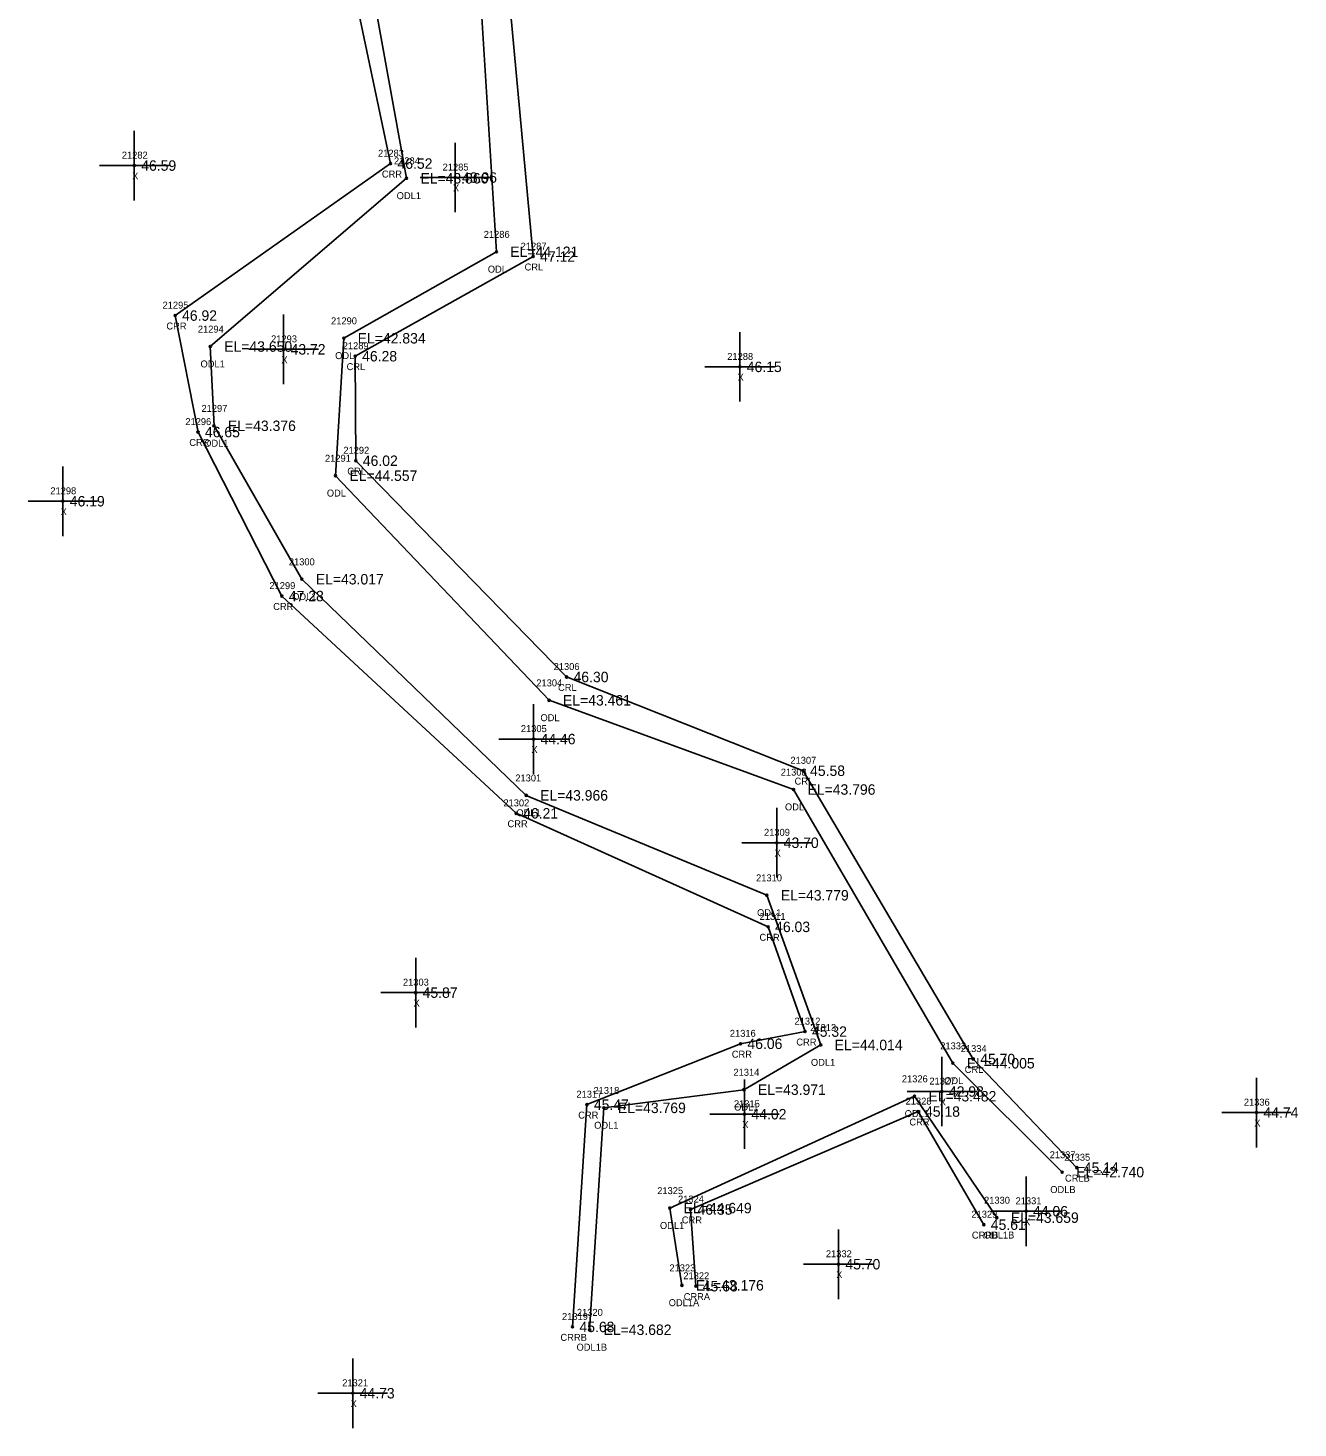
# Model space of a CAD drawing. Extents: x 2420351 to 2422725, y 845330 to 846558.
# Drawn here: x 2421764.6 to 2421947.1, y 845330.1 to 845531.3 of the extents above; entities that cross this region are included whole.
import ezdxf

# ---------------------------------------------------------------- set-up
doc = ezdxf.new("R2010")
doc.units = 0
for name, color, linetype in [('RD_EX_H2O', 7, 'Continuous'), ('RD_EX_H2O_txCode', 7, 'Continuous'), ('RD_EX_Misc', 7, 'Continuous'), ('RD_EX_Misc_txCode', 7, 'Continuous'), ('RD_EX_TX_H2O_ELEV', 7, 'Continuous'), ('RD_EX_TX_Misc_ELEV', 7, 'Continuous'), ('RD_SMD_Locator', 7, 'Continuous')]:
    doc.layers.add(name, color=color, linetype=linetype)

msp = doc.modelspace()

# ---------------------------------------------------------------- linework, layer by layer
at = {"layer": 'RD_EX_H2O'}
for points in [[(2421789.64, 845837.83), (2421802.06, 845811.15), (2421810.66, 845784.93), (2421844.56, 845740.42), (2421856.1, 845683.72), (2421854.89, 845664.88), (2421843.25, 845658.16), (2421829.21, 845628.83), (2421830.77, 845610.33), (2421843.38, 845580.1), (2421828.19, 845558.94), (2421831.91, 845499.14), (2421809.98, 845486.71), (2421808.79, 845466.96), (2421839.47, 845434.68), (2421874.6, 845421.86), (2421897.47, 845382.52), (2421913.19, 845366.87)], [(2421810.77, 845819.82), (2421810.76, 845810.56), (2421816.9, 845792.5), (2421822.4, 845786.03), (2421848.72, 845738.63), (2421858.75, 845685.13), (2421860.35, 845662.88), (2421845.9, 845650.47), (2421833.11, 845629.75), (2421840.79, 845614.06), (2421848.44, 845579.41), (2421832.04, 845554.52), (2421837.19, 845498.45), (2421811.62, 845484.13), (2421811.72, 845469.11), (2421841.99, 845438.03), (2421875.97, 845424.56), (2421900.41, 845383.13), (2421915.29, 845367.51)], [(2421769.97, 845784.59), (2421775.7, 845782.12), (2421786.73, 845771.94), (2421823.71, 845730.54), (2421836.28, 845679.34), (2421832.24, 845660.92), (2421820.77, 845638.45), (2421823.1, 845608.96), (2421831.71, 845583.35), (2421823.31, 845575.86), (2421811.92, 845548.94), (2421818.99, 845509.7), (2421790.81, 845485.52), (2421791.34, 845474.13), (2421803.96, 845452.08), (2421836.18, 845421.02), (2421870.76, 845406.66), (2421878.5, 845385.15), (2421867.47, 845378.72), (2421847.36, 845376.11), (2421845.3, 845344.22)], [(2421768.08, 845778.29), (2421776.13, 845776.03), (2421785.06, 845769.58), (2421818.61, 845726.06), (2421831.42, 845677.9), (2421825.05, 845663.86), (2421816.1, 845638.14), (2421820.64, 845608.52), (2421828.09, 845585.14), (2421817.9, 845575.21), (2421808.75, 845549.61), (2421816.7, 845511.81), (2421785.75, 845489.97), (2421789.04, 845473.23), (2421801.09, 845449.66), (2421834.75, 845418.44), (2421870.95, 845402.12), (2421876.24, 845387.07), (2421866.97, 845385.32), (2421844.91, 845376.57), (2421842.84, 845344.63)], [(2421858.56, 845350.61), (2421856.81, 845361.71), (2421891.97, 845377.78), (2421903.8, 845360.33)], [(2421860.55, 845350.48), (2421859.8, 845361.5), (2421892.48, 845375.58), (2421901.93, 845359.32)]]:
    msp.add_lwpolyline(points, dxfattribs=at)
at = {"layer": 'RD_EX_Misc'}
for p, q in [((2421779.89, 845506.53), (2421779.89, 845516.53)), ((2421825.97, 845504.81), (2421825.97, 845514.81)), ((2421774.89, 845511.53), (2421784.89, 845511.53)), ((2421820.97, 845509.81), (2421830.97, 845509.81)), ((2421801.34, 845480.12), (2421801.34, 845490.12)), ((2421866.87, 845477.6), (2421866.87, 845487.6)), ((2421796.34, 845485.12), (2421806.34, 845485.12)), ((2421861.87, 845482.6), (2421871.87, 845482.6)), ((2421769.62, 845458.29), (2421769.62, 845468.29)), ((2421764.62, 845463.29), (2421774.62, 845463.29)), ((2421837.25, 845424.11), (2421837.25, 845434.11)), ((2421832.25, 845429.11), (2421842.25, 845429.11)), ((2421872.18, 845409.21), (2421872.18, 845419.21)), ((2421867.18, 845414.21), (2421877.18, 845414.21)), ((2421820.31, 845387.67), (2421820.31, 845397.67)), ((2421815.31, 845392.67), (2421825.31, 845392.67)), ((2421895.91, 845373.46), (2421895.91, 845383.46)), ((2421867.55, 845370.2), (2421867.55, 845380.2)), ((2421941.1, 845370.43), (2421941.1, 845380.43)), ((2421890.91, 845378.46), (2421900.91, 845378.46)), ((2421862.55, 845375.2), (2421872.55, 845375.2)), ((2421936.1, 845375.43), (2421946.1, 845375.43)), ((2421908, 845356.25), (2421908, 845366.25)), ((2421903, 845361.25), (2421913, 845361.25)), ((2421881.04, 845348.64), (2421881.04, 845358.64)), ((2421876.04, 845353.64), (2421886.04, 845353.64)), ((2421811.27, 845330.1), (2421811.27, 845340.1)), ((2421806.27, 845335.1), (2421816.27, 845335.1))]:
    msp.add_line(p, q, dxfattribs=at)
at = {"layer": 'RD_SMD_Locator'}
for centre in [(2421779.89, 845511.53), (2421816.7, 845511.81), (2421818.99, 845509.7), (2421825.97, 845509.81), (2421831.91, 845499.14), (2421837.19, 845498.45), (2421785.75, 845489.97), (2421790.81, 845485.52), (2421801.34, 845485.12), (2421809.98, 845486.71), (2421811.62, 845484.13), (2421866.87, 845482.6), (2421789.04, 845473.23), (2421791.34, 845474.13), (2421811.72, 845469.11), (2421808.79, 845466.96), (2421769.62, 845463.29), (2421803.96, 845452.08), (2421801.09, 845449.66), (2421841.99, 845438.03), (2421839.47, 845434.68), (2421837.25, 845429.11), (2421875.97, 845424.56), (2421836.18, 845421.02), (2421874.6, 845421.86), (2421834.75, 845418.44), (2421872.18, 845414.21), (2421870.76, 845406.66), (2421870.95, 845402.12), (2421820.31, 845392.67), (2421876.24, 845387.07), (2421866.97, 845385.32), (2421878.5, 845385.15), (2421897.47, 845382.52), (2421900.41, 845383.13), (2421867.47, 845378.72), (2421895.91, 845378.46), (2421844.91, 845376.57), (2421891.97, 845377.78), (2421847.36, 845376.11), (2421867.55, 845375.2), (2421892.48, 845375.58), (2421941.1, 845375.43), (2421913.19, 845366.87), (2421915.29, 845367.51), (2421856.81, 845361.71), (2421859.8, 845361.5), (2421903.8, 845360.33), (2421908, 845361.25), (2421901.93, 845359.32), (2421881.04, 845353.64), (2421858.56, 845350.61), (2421860.55, 845350.48), (2421842.84, 845344.63), (2421845.3, 845344.22), (2421811.27, 845335.1)]:
    msp.add_circle(centre, 0.15, dxfattribs=at)

# ---------------------------------------------------------------- texts
at = {"layer": 'RD_EX_H2O_txCode'}
for s, p in [('21283', (2421814.9, 845512.81)), ('21284', (2421817.19, 845511.7)), ('CRR', (2421815.45, 845509.81)), ('ODL1', (2421817.58, 845506.7)), ('21286', (2421830.09, 845501.14)), ('21287', (2421835.39, 845499.45)), ('CRL', (2421835.96, 845496.45)), ('ODL', (2421830.67, 845496.14)), ('21295', (2421783.95, 845490.97)), ('21290', (2421808.15, 845488.71)), ('CRR', (2421784.5, 845487.97)), ('21294', (2421789.02, 845487.52)), ('21289', (2421809.83, 845485.13)), ('ODL1', (2421789.4, 845482.52)), ('ODL', (2421808.74, 845483.71)), ('CRL', (2421810.39, 845482.13)), ('21297', (2421789.54, 845476.13)), ('21296', (2421787.22, 845474.23)), ('CRR', (2421787.79, 845471.23)), ('ODL1', (2421789.93, 845471.13)), ('21292', (2421809.92, 845470.11)), ('21291', (2421807.28, 845468.96)), ('CRL', (2421810.49, 845467.11)), ('ODL', (2421807.55, 845463.96)), ('21300', (2421802.09, 845454.08)), ('21299', (2421799.3, 845450.66)), ('ODL1', (2421802.56, 845449.08)), ('CRR', (2421799.84, 845447.66)), ('21306', (2421840.13, 845439.03)), ('21304', (2421837.64, 845436.68)), ('CRL', (2421840.76, 845436.03)), ('ODL', (2421838.23, 845431.68)), ('21308', (2421872.76, 845423.86)), ('21307', (2421874.14, 845425.56)), ('21301', (2421834.62, 845423.02)), ('CRL', (2421874.74, 845422.56)), ('21302', (2421832.91, 845419.44)), ('ODL1', (2421834.77, 845418.02)), ('ODL', (2421873.36, 845418.86)), ('CRR', (2421833.5, 845416.44)), ('21310', (2421869.21, 845408.66)), ('ODL1', (2421869.35, 845403.66)), ('21311', (2421869.72, 845403.12)), ('CRR', (2421869.7, 845400.12)), ('21312', (2421874.73, 845388.07)), ('21316', (2421865.44, 845386.32)), ('21313', (2421876.99, 845387.15)), ('CRR', (2421874.99, 845385.07)), ('21333', (2421895.67, 845384.52)), ('21334', (2421898.61, 845384.13)), ('CRR', (2421865.72, 845383.32)), ('ODL1', (2421877.09, 845382.15)), ('21314', (2421865.96, 845380.72)), ('21326', (2421890.15, 845379.78)), ('ODL', (2421896.23, 845379.52)), ('CRL', (2421899.18, 845381.13)), ('21317', (2421843.4, 845377.57)), ('21318', (2421845.85, 845378.11)), ('ODL1', (2421866.06, 845375.72)), ('21328', (2421890.69, 845376.58)), ('CRR', (2421843.66, 845374.57)), ('ODL1', (2421890.56, 845374.78)), ('CRR', (2421891.23, 845373.58)), ('ODL1', (2421845.95, 845373.11)), ('21337', (2421911.39, 845368.87)), ('21335', (2421913.49, 845368.51)), ('CRLB', (2421913.59, 845365.51)), ('21325', (2421855.01, 845363.71)), ('ODLB', (2421911.47, 845363.87)), ('21324', (2421858, 845362.5)), ('21330', (2421901.96, 845362.33)), ('CRR', (2421858.54, 845359.5)), ('21329', (2421900.14, 845360.32)), ('ODL1', (2421855.4, 845358.71)), ('CRRB', (2421900.21, 845357.32)), ('ODL1B', (2421901.92, 845357.33)), ('21323', (2421856.76, 845352.61)), ('21322', (2421858.76, 845351.48)), ('ODL1A', (2421856.66, 845347.61)), ('CRRA', (2421858.81, 845348.48)), ('21319', (2421841.33, 845345.63)), ('21320', (2421843.47, 845346.22)), ('CRRB', (2421841.11, 845342.63)), ('ODL1B', (2421843.42, 845341.22))]:
    msp.add_text(s, height=1, dxfattribs=at).set_placement(p)
at = {"layer": 'RD_EX_Misc_txCode'}
for s, p in [('21282', (2421778.1, 845512.53)), ('21285', (2421824.18, 845510.81)), ('X', (2421779.58, 845509.53)), ('X', (2421825.66, 845507.81)), ('21293', (2421799.54, 845486.12)), ('X', (2421801.02, 845483.12)), ('21288', (2421865.07, 845483.6)), ('X', (2421866.55, 845480.6)), ('21298', (2421767.83, 845464.29)), ('X', (2421769.31, 845461.29)), ('21305', (2421835.42, 845430.11)), ('X', (2421836.93, 845427.11)), ('21309', (2421870.35, 845415.21)), ('X', (2421871.87, 845412.21)), ('21303', (2421818.48, 845393.67)), ('X', (2421820, 845390.67)), ('21327', (2421894.11, 845379.46)), ('21315', (2421866.03, 845376.2)), ('X', (2421895.59, 845376.46)), ('21336', (2421939.28, 845376.43)), ('X', (2421867.23, 845373.2)), ('X', (2421940.78, 845373.43)), ('21331', (2421906.49, 845362.25)), ('X', (2421907.69, 845359.25)), ('21332', (2421879.24, 845354.64)), ('X', (2421880.72, 845351.64)), ('21321', (2421809.76, 845336.1)), ('X', (2421810.96, 845333.1))]:
    msp.add_text(s, height=1, dxfattribs=at).set_placement(p)
at = {"layer": 'RD_EX_TX_H2O_ELEV'}
for s, p in [('46.52', (2421817.7, 845511.06)), ('EL=43.866', (2421820.99, 845508.95)), ('EL=44.121', (2421833.91, 845498.39)), ('47.12', (2421838.19, 845497.7)), ('46.92', (2421786.75, 845489.22)), ('EL=42.834', (2421811.98, 845485.96)), ('EL=43.650', (2421792.81, 845484.77)), ('46.28', (2421812.62, 845483.38)), ('46.65', (2421790.04, 845472.48)), ('EL=43.376', (2421793.34, 845473.38)), ('46.02', (2421812.72, 845468.36)), ('EL=44.557', (2421810.79, 845466.21)), ('EL=43.017', (2421805.96, 845451.33)), ('47.28', (2421802.09, 845448.91)), ('46.30', (2421842.99, 845437.28)), ('EL=43.461', (2421841.47, 845433.93)), ('45.58', (2421876.97, 845423.81)), ('EL=43.966', (2421838.18, 845420.27)), ('EL=43.796', (2421876.6, 845421.11)), ('46.21', (2421835.75, 845417.69)), ('EL=43.779', (2421872.76, 845405.91)), ('46.03', (2421871.95, 845401.37)), ('45.32', (2421877.24, 845386.32)), ('46.06', (2421867.97, 845384.57)), ('EL=44.014', (2421880.5, 845384.4)), ('EL=44.005', (2421899.47, 845381.77)), ('45.70', (2421901.41, 845382.38)), ('EL=43.971', (2421869.47, 845377.97)), ('EL=43.482', (2421893.97, 845377.03)), ('45.47', (2421845.91, 845375.82)), ('EL=43.769', (2421849.36, 845375.36)), ('45.18', (2421893.48, 845374.83)), ('EL=42.740', (2421915.19, 845366.12)), ('45.14', (2421916.29, 845366.76)), ('EL=44.649', (2421858.81, 845360.96)), ('46.35', (2421860.8, 845360.75)), ('EL=43.659', (2421905.8, 845359.58)), ('45.61', (2421902.93, 845358.57)), ('EL=43.176', (2421860.56, 845349.86)), ('45.68', (2421861.55, 845349.73)), ('45.68', (2421843.84, 845343.88)), ('EL=43.682', (2421847.3, 845343.47))]:
    msp.add_text(s, height=1.5, dxfattribs=at).set_placement(p)
at = {"layer": 'RD_EX_TX_Misc_ELEV'}
for s, p in [('46.59', (2421780.89, 845510.78)), ('43.96', (2421826.97, 845509.06)), ('43.72', (2421802.34, 845484.37)), ('46.15', (2421867.87, 845481.85)), ('46.19', (2421770.62, 845462.54)), ('44.46', (2421838.25, 845428.36)), ('43.70', (2421873.18, 845413.46)), ('45.87', (2421821.31, 845391.92)), ('42.98', (2421896.91, 845377.71)), ('44.02', (2421868.55, 845374.45)), ('44.74', (2421942.1, 845374.68)), ('44.06', (2421909, 845360.5)), ('45.70', (2421882.04, 845352.89)), ('44.73', (2421812.27, 845334.35))]:
    msp.add_text(s, height=1.5, dxfattribs=at).set_placement(p)

doc.saveas('drawing.dxf')
